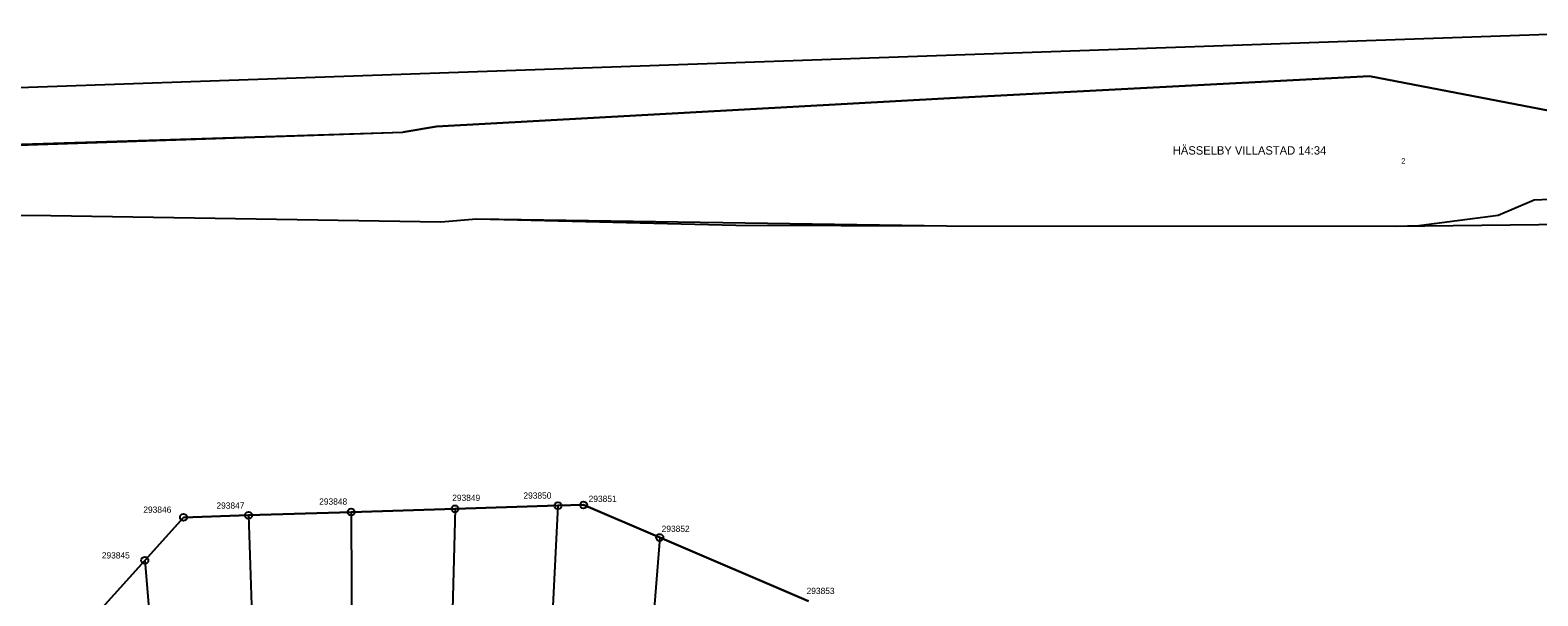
# Model space of a CAD drawing. Extents: x 141995 to 152570, y 6580184 to 6586000.
# Drawn here: x 142574.5 to 142790.9, y 6585783.8 to 6585865 of the extents above; entities that cross this region are included whole.
import ezdxf

# ---------------------------------------------------------------- set-up
doc = ezdxf.new("R2010")
doc.units = 0
for name, color, linetype in [('Level 10', 7, 'Continuous'), ('Level 21', 7, 'Continuous'), ('Level 5', 7, 'Continuous'), ('Level 51', 7, 'Continuous'), ('Level 53', 7, 'Continuous'), ('Level 6', 7, 'Continuous'), ('Level 7', 7, 'Continuous')]:
    doc.layers.add(name, color=color, linetype=linetype)

msp = doc.modelspace()

# ---------------------------------------------------------------- linework, layer by layer
at = {"layer": 'Level 10'}
for centre in [(142650.23, 6585796.72), (142653.9, 6585796.83), (142596.49, 6585795.04), (142605.81, 6585795.33), (142620.55, 6585795.79), (142635.45, 6585796.26), (142664.84, 6585792.14), (142590.93, 6585788.85)]:
    msp.add_circle(centre, 0.5, dxfattribs=at)
at = {"layer": 'Level 21'}
for points in [[(142766.7, 6585858.4), (142706.47, 6585855.26)], [(142792.56, 6585853.43), (142766.7, 6585858.4)], [(142706.47, 6585855.26), (142632.79, 6585851.2)], [(142526.16, 6585847.14), (142627.98, 6585850.39)], [(142632.79, 6585851.2), (142627.98, 6585850.39)]]:
    msp.add_lwpolyline(points, dxfattribs=at)
at = {"layer": 'Level 5'}
for points in [[(142706.47, 6585855.26), (142766.7, 6585858.4)], [(142766.7, 6585858.4), (142792.56, 6585853.43)], [(142632.79, 6585851.2), (142706.47, 6585855.26)], [(142552.89, 6585847.83), (142627.98, 6585850.39)], [(142627.98, 6585850.39), (142632.79, 6585851.2)], [(142545.85, 6585838.47), (142577.43, 6585838.39)], [(142577.43, 6585838.39), (142633.4, 6585837.48)], [(142633.4, 6585837.48), (142638.53, 6585837.93)], [(142638.53, 6585837.93), (142675.73, 6585837.01)], [(142675.73, 6585837.01), (142705.99, 6585836.9)], [(142705.99, 6585836.9), (142770.54, 6585836.86)], [(142770.54, 6585836.86), (142799.19, 6585837.2)], [(142596.49, 6585795.04), (142605.81, 6585795.33)], [(142605.81, 6585795.33), (142620.55, 6585795.79)], [(142620.55, 6585795.79), (142635.45, 6585796.26)], [(142635.45, 6585796.26), (142650.23, 6585796.72)], [(142650.23, 6585796.72), (142653.9, 6585796.83)], [(142653.9, 6585796.83), (142664.84, 6585792.14)], [(142590.93, 6585788.85), (142596.49, 6585795.04)], [(142664.84, 6585792.14), (142686.17, 6585783.01)], [(142575.11, 6585771.27), (142590.93, 6585788.85)]]:
    msp.add_lwpolyline(points, dxfattribs=at)
at = {"layer": 'Level 6'}
for points in [[(143000, 6585862.54), (142951.18, 6585863.09), (142826.64, 6585863.23), (142810.19, 6585865.03), (142526.15, 6585855.09), (142526.16, 6585847.14), (142497.73, 6585846.62), (142455.06, 6585845.78), (142450.19, 6585846.22), (142436.31, 6585845.91), (142416.82, 6585845.62), (142406.79, 6585845.47), (142365.61, 6585844.86), (142354.53, 6585843.6), (142347.46, 6585843.44), (142347.66, 6585852.15), (142029.5, 6585846.1), (142000, 6585845.22)], [(142416.89, 6585836.01), (142445.48, 6585836.91), (142448.57, 6585836.74), (142496.48, 6585837.35), (142545.85, 6585838.47), (142577.43, 6585838.39), (142633.4, 6585837.48), (142638.53, 6585837.93), (142705.99, 6585836.9), (142770.54, 6585836.86), (142773.76, 6585836.98), (142785.14, 6585838.45), (142790.32, 6585840.63), (142794.8, 6585840.84), (142848.36, 6585837.76), (142869.99, 6585838.07), (142946.64, 6585840.47), (143000, 6585842.14)], [(142686.17, 6585783.01), (142664.84, 6585792.14), (142653.9, 6585796.83), (142650.23, 6585796.72), (142635.45, 6585796.26), (142620.55, 6585795.79), (142605.81, 6585795.33), (142596.49, 6585795.04), (142590.93, 6585788.85), (142575.11, 6585771.27)]]:
    msp.add_lwpolyline(points, dxfattribs=at)
at = {"layer": 'Level 7'}
for points in [[(142605.81, 6585795.33), (142607.24, 6585752.27)], [(142620.55, 6585795.79), (142620.73, 6585752.83)], [(142635.45, 6585796.26), (142634.34, 6585752.85)], [(142650.23, 6585796.72), (142648.03, 6585752.42)], [(142664.84, 6585792.14), (142661.64, 6585752)], [(142590.93, 6585788.85), (142594.08, 6585751.15)]]:
    msp.add_lwpolyline(points, dxfattribs=at)

# ---------------------------------------------------------------- texts
at = {"layer": 'Level 51'}
for s, height, p in [('HÄSSELBY VILLASTAD 14:34', 1.2, (142738.46, 6585847.15)), ('2', 0.8, (142771.25, 6585845.84))]:
    msp.add_text(s, height=height, dxfattribs=at).set_placement(p)
at = {"layer": 'Level 53'}
for s, rotation, p in [('293848', 0.0451, (142615.96, 6585796.86)), ('293849', 0.0451, (142635.05, 6585797.4)), ('293850', 0.0451, (142645.27, 6585797.72)), ('293851', 0.0451, (142654.63, 6585797.25)), ('293846', 0.0451, (142590.72, 6585795.69)), ('293847', 0.0451, (142601.21, 6585796.28)), ('293852', 0.0485, (142665.11, 6585792.95)), ('293845', 0.0451, (142584.76, 6585789.13)), ('293853', 0.0485, (142685.91, 6585784.02))]:
    msp.add_text(s, height=0.9, rotation=rotation, dxfattribs=at).set_placement(p)

doc.saveas('drawing.dxf')
